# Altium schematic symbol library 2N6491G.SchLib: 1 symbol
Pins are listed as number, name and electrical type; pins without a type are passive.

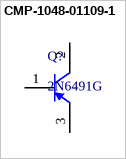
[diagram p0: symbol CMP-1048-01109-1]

## CMP-1048-01109-1
designator Q?, comment 2N6491G
Complementary Silicon Plastic Power Transistor, 3-Pin TO-220, Pb-Free, Tube; Manufacturer: On Semiconductor; fT Min (MHz): 5; Polarity: PNP; IC Continuous (A): 15
footprint ONSC-TO-220-3-221A-09 (FM, 3-Leads, Body 10.3x4.85mm, Pitch 2.54mm)
pins: 1 B, 2 C, 3 E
